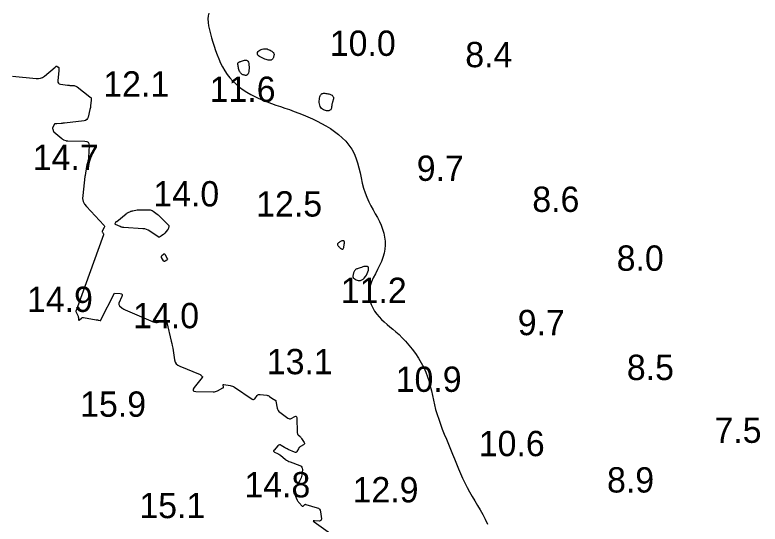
# Model space of a CAD drawing. Extents: x 3040093 to 3056816, y 408076 to 509144.
# Drawn here: x 3044690.5 to 3044837.6, y 435320 to 435420.6 of the extents above; entities that cross this region are included whole.
import ezdxf

# ---------------------------------------------------------------- set-up
doc = ezdxf.new("R2010")
doc.units = 0
for name, color, linetype in [('V-CHAN-CONT-EL12-1112', 7, 'Continuous'), ('V-CHAN-CONT-EL15', 7, 'Continuous'), ('V-TOPO-SOUN-0810', 7, 'Continuous')]:
    doc.layers.add(name, color=color, linetype=linetype)

msp = doc.modelspace()

# ---------------------------------------------------------------- linework, layer by layer
at = {"layer": 'V-CHAN-CONT-EL12-1112'}
msp.add_lwpolyline([(3044728.77, 435420.93), (3044728.62, 435420.39), (3044728.58, 435419.79), (3044728.61, 435419.12), (3044728.71, 435418.41), (3044728.87, 435417.65), (3044729.07, 435416.86), (3044729.3, 435416.05), (3044729.55, 435415.22), (3044729.82, 435414.39), (3044730.1, 435413.55), (3044730.39, 435412.72), (3044730.72, 435411.9), (3044731.07, 435411.09), (3044731.46, 435410.31), (3044731.9, 435409.56), (3044732.38, 435408.84), (3044732.92, 435408.15), (3044733.51, 435407.51), (3044734.15, 435406.91), (3044734.82, 435406.34), (3044735.54, 435405.82), (3044736.28, 435405.33), (3044737.05, 435404.88), (3044737.84, 435404.46), (3044738.64, 435404.08), (3044739.47, 435403.73), (3044740.3, 435403.4), (3044741.15, 435403.09), (3044742.02, 435402.79), (3044742.89, 435402.49), (3044743.78, 435402.19), (3044744.68, 435401.88), (3044745.58, 435401.55), (3044746.5, 435401.21), (3044747.41, 435400.84), (3044748.32, 435400.46), (3044749.23, 435400.05), (3044750.13, 435399.61), (3044751.02, 435399.15), (3044751.89, 435398.66), (3044752.75, 435398.13), (3044753.57, 435397.57), (3044754.36, 435396.97), (3044755.1, 435396.32), (3044755.79, 435395.63), (3044756.41, 435394.89), (3044756.96, 435394.1), (3044757.43, 435393.25), (3044757.81, 435392.34), (3044758.13, 435391.39), (3044758.39, 435390.4), (3044758.62, 435389.4), (3044758.84, 435388.39), (3044759.06, 435387.39), (3044759.3, 435386.41), (3044759.59, 435385.47), (3044759.93, 435384.57), (3044760.32, 435383.71), (3044760.74, 435382.89), (3044761.18, 435382.1), (3044761.62, 435381.32), (3044762.04, 435380.56), (3044762.43, 435379.8), (3044762.78, 435379.05), (3044763.07, 435378.28), (3044763.3, 435377.5), (3044763.46, 435376.72), (3044763.55, 435375.93), (3044763.57, 435375.13), (3044763.51, 435374.33), (3044763.37, 435373.53), (3044763.14, 435372.72), (3044762.83, 435371.91), (3044762.45, 435371.1), (3044762.04, 435370.29), (3044761.63, 435369.49), (3044761.23, 435368.69), (3044760.88, 435367.9), (3044760.6, 435367.12), (3044760.42, 435366.35), (3044760.35, 435365.59), (3044760.4, 435364.84), (3044760.55, 435364.12), (3044760.79, 435363.42), (3044761.11, 435362.75), (3044761.48, 435362.11), (3044761.91, 435361.51), (3044762.38, 435360.96), (3044762.87, 435360.44), (3044763.39, 435359.96), (3044763.94, 435359.49), (3044764.5, 435359.02), (3044765.08, 435358.54), (3044765.69, 435358.03), (3044766.31, 435357.47), (3044766.95, 435356.85), (3044767.6, 435356.15), (3044768.25, 435355.39), (3044768.9, 435354.58), (3044769.53, 435353.72), (3044770.12, 435352.83), (3044770.67, 435351.91), (3044771.17, 435350.98), (3044771.6, 435350.05), (3044771.95, 435349.12), (3044772.24, 435348.21), (3044772.48, 435347.29), (3044772.7, 435346.38), (3044772.89, 435345.46), (3044773.08, 435344.54), (3044773.29, 435343.61), (3044773.53, 435342.67), (3044773.81, 435341.71), (3044774.13, 435340.75), (3044774.48, 435339.77), (3044774.85, 435338.79), (3044775.24, 435337.81), (3044775.65, 435336.82), (3044776.05, 435335.84), (3044776.45, 435334.85), (3044776.85, 435333.88), (3044777.24, 435332.91), (3044777.63, 435331.94), (3044778.02, 435330.99), (3044778.43, 435330.04), (3044778.85, 435329.11), (3044779.29, 435328.19), (3044779.75, 435327.29), (3044780.24, 435326.39), (3044780.75, 435325.51), (3044781.27, 435324.62), (3044781.8, 435323.74), (3044782.32, 435322.84), (3044782.83, 435321.93), (3044783.31, 435321), (3044783.76, 435320.04)], dxfattribs=at)
for points in [[(3044739.8, 435413.92), (3044740.03, 435413.9), (3044740.26, 435413.86), (3044740.48, 435413.79), (3044740.69, 435413.7), (3044740.88, 435413.61), (3044741.05, 435413.51), (3044741.19, 435413.41), (3044741.32, 435413.32), (3044741.42, 435413.24), (3044741.5, 435413.16), (3044741.55, 435413.08), (3044741.6, 435413), (3044741.62, 435412.91), (3044741.63, 435412.82), (3044741.63, 435412.71), (3044741.62, 435412.59), (3044741.59, 435412.47), (3044741.56, 435412.33), (3044741.51, 435412.2), (3044741.46, 435412.07), (3044741.4, 435411.95), (3044741.32, 435411.85), (3044741.24, 435411.76), (3044741.15, 435411.7), (3044741.05, 435411.65), (3044740.93, 435411.63), (3044740.8, 435411.63), (3044740.65, 435411.64), (3044740.47, 435411.68), (3044740.28, 435411.73), (3044740.05, 435411.8), (3044739.81, 435411.88), (3044739.54, 435411.98), (3044739.27, 435412.1), (3044739.02, 435412.22), (3044738.78, 435412.36), (3044738.59, 435412.51), (3044738.44, 435412.66), (3044738.36, 435412.83), (3044738.34, 435413), (3044738.4, 435413.18), (3044738.51, 435413.35), (3044738.66, 435413.5), (3044738.85, 435413.65), (3044739.07, 435413.76), (3044739.31, 435413.85), (3044739.55, 435413.91)], [(3044734.76, 435409.59), (3044734.69, 435409.79), (3044734.64, 435410), (3044734.59, 435410.21), (3044734.55, 435410.42), (3044734.53, 435410.61), (3044734.51, 435410.79), (3044734.51, 435410.94), (3044734.52, 435411.05), (3044734.55, 435411.14), (3044734.59, 435411.21), (3044734.65, 435411.25), (3044734.73, 435411.29), (3044734.82, 435411.33), (3044734.94, 435411.37), (3044735.08, 435411.42), (3044735.24, 435411.48), (3044735.42, 435411.55), (3044735.61, 435411.62), (3044735.8, 435411.66), (3044735.99, 435411.68), (3044736.17, 435411.66), (3044736.33, 435411.58), (3044736.46, 435411.45), (3044736.57, 435411.24), (3044736.64, 435410.98), (3044736.69, 435410.68), (3044736.71, 435410.36), (3044736.71, 435410.03), (3044736.68, 435409.71), (3044736.64, 435409.41), (3044736.58, 435409.16), (3044736.51, 435408.96), (3044736.42, 435408.82), (3044736.33, 435408.72), (3044736.22, 435408.66), (3044736.11, 435408.64), (3044735.99, 435408.64), (3044735.86, 435408.66), (3044735.74, 435408.7), (3044735.61, 435408.74), (3044735.49, 435408.79), (3044735.37, 435408.85), (3044735.25, 435408.92), (3044735.14, 435409.02), (3044735.03, 435409.12), (3044734.93, 435409.26), (3044734.84, 435409.41)], [(3044750.83, 435404.77), (3044750.92, 435404.9), (3044751.02, 435405), (3044751.13, 435405.06), (3044751.25, 435405.1), (3044751.38, 435405.12), (3044751.53, 435405.12), (3044751.69, 435405.11), (3044751.87, 435405.09), (3044752.05, 435405.06), (3044752.25, 435405.03), (3044752.44, 435404.99), (3044752.62, 435404.94), (3044752.79, 435404.88), (3044752.94, 435404.81), (3044753.08, 435404.73), (3044753.18, 435404.64), (3044753.26, 435404.55), (3044753.31, 435404.44), (3044753.35, 435404.33), (3044753.36, 435404.22), (3044753.36, 435404.1), (3044753.35, 435403.98), (3044753.33, 435403.87), (3044753.3, 435403.75), (3044753.27, 435403.64), (3044753.23, 435403.52), (3044753.19, 435403.41), (3044753.15, 435403.3), (3044753.11, 435403.19), (3044753.08, 435403.07), (3044753.06, 435402.96), (3044753.04, 435402.84), (3044753.02, 435402.72), (3044753.02, 435402.6), (3044753.01, 435402.49), (3044753, 435402.38), (3044752.98, 435402.27), (3044752.96, 435402.16), (3044752.93, 435402.06), (3044752.88, 435401.97), (3044752.83, 435401.88), (3044752.75, 435401.81), (3044752.67, 435401.75), (3044752.56, 435401.7), (3044752.44, 435401.66), (3044752.3, 435401.64), (3044752.14, 435401.65), (3044751.97, 435401.67), (3044751.77, 435401.71), (3044751.58, 435401.78), (3044751.38, 435401.87), (3044751.19, 435401.99), (3044751.01, 435402.13), (3044750.86, 435402.31), (3044750.74, 435402.52), (3044750.65, 435402.77), (3044750.59, 435403.03), (3044750.57, 435403.32), (3044750.57, 435403.6), (3044750.59, 435403.89), (3044750.63, 435404.15), (3044750.69, 435404.4), (3044750.75, 435404.61)], [(3044755.2, 435374.33), (3044755.26, 435374.37), (3044755.31, 435374.43), (3044755.36, 435374.53), (3044755.39, 435374.64), (3044755.42, 435374.76), (3044755.44, 435374.9), (3044755.47, 435375.04), (3044755.49, 435375.2), (3044755.51, 435375.35), (3044755.53, 435375.49), (3044755.53, 435375.62), (3044755.52, 435375.75), (3044755.5, 435375.85), (3044755.45, 435375.93), (3044755.38, 435375.98), (3044755.28, 435375.99), (3044755.15, 435375.98), (3044755.02, 435375.95), (3044754.88, 435375.9), (3044754.73, 435375.83), (3044754.59, 435375.76), (3044754.46, 435375.68), (3044754.35, 435375.6), (3044754.27, 435375.53), (3044754.21, 435375.46), (3044754.17, 435375.39), (3044754.16, 435375.32), (3044754.16, 435375.25), (3044754.19, 435375.17), (3044754.24, 435375.09), (3044754.31, 435374.99), (3044754.39, 435374.89), (3044754.49, 435374.78), (3044754.59, 435374.67), (3044754.71, 435374.56), (3044754.82, 435374.47), (3044754.93, 435374.39), (3044755.03, 435374.34), (3044755.12, 435374.32)], [(3044760.19, 435370.82), (3044760.05, 435370.91), (3044759.86, 435370.94), (3044759.63, 435370.93), (3044759.39, 435370.89), (3044759.13, 435370.82), (3044758.88, 435370.74), (3044758.65, 435370.67), (3044758.44, 435370.6), (3044758.25, 435370.54), (3044758.09, 435370.48), (3044757.96, 435370.42), (3044757.83, 435370.36), (3044757.73, 435370.29), (3044757.64, 435370.22), (3044757.56, 435370.13), (3044757.49, 435370.03), (3044757.43, 435369.92), (3044757.38, 435369.8), (3044757.34, 435369.67), (3044757.3, 435369.55), (3044757.27, 435369.42), (3044757.24, 435369.3), (3044757.23, 435369.18), (3044757.21, 435369.08), (3044757.21, 435368.98), (3044757.21, 435368.89), (3044757.23, 435368.81), (3044757.28, 435368.72), (3044757.34, 435368.64), (3044757.42, 435368.55), (3044757.54, 435368.47), (3044757.68, 435368.38), (3044757.85, 435368.29), (3044758.05, 435368.22), (3044758.26, 435368.17), (3044758.49, 435368.15), (3044758.72, 435368.18), (3044758.96, 435368.27), (3044759.2, 435368.42), (3044759.44, 435368.63), (3044759.66, 435368.91), (3044759.87, 435369.22), (3044760.04, 435369.54), (3044760.18, 435369.87), (3044760.27, 435370.18), (3044760.31, 435370.45), (3044760.28, 435370.67)]]:
    msp.add_lwpolyline(points, close=True, dxfattribs=at)
at = {"layer": 'V-CHAN-CONT-EL15'}
for points in [[(3044690.03, 435408.49), (3044694.68, 435408.02), (3044695.13, 435408.01), (3044695.55, 435408.09), (3044695.95, 435408.26), (3044696.32, 435408.52), (3044698.41, 435410.25), (3044698.44, 435410.27), (3044698.47, 435410.3), (3044698.5, 435410.33), (3044698.52, 435410.35), (3044698.63, 435410.46), (3044698.65, 435410.48), (3044698.68, 435410.49), (3044698.71, 435410.49), (3044698.75, 435410.48), (3044699.06, 435410.3), (3044699.11, 435410.26), (3044699.14, 435410.22), (3044699.16, 435410.17), (3044699.17, 435410.11), (3044699.18, 435409.85), (3044699.18, 435409.79), (3044699.18, 435409.72), (3044699.17, 435409.66), (3044699.17, 435409.59), (3044698.98, 435407.55), (3044698.99, 435407.3), (3044699.08, 435407.11), (3044699.24, 435406.98), (3044699.49, 435406.91), (3044700.86, 435406.73), (3044701.03, 435406.71), (3044701.19, 435406.69), (3044701.36, 435406.68), (3044701.52, 435406.66), (3044702.18, 435406.62), (3044702.34, 435406.59), (3044702.49, 435406.55), (3044702.64, 435406.48), (3044702.77, 435406.39), (3044705.26, 435404.42), (3044705.28, 435404.4), (3044705.31, 435404.38), (3044705.34, 435404.36), (3044705.36, 435404.34), (3044705.47, 435404.27), (3044705.5, 435404.25), (3044705.52, 435404.23), (3044705.53, 435404.2), (3044705.53, 435404.17), (3044705.55, 435403.92), (3044705.55, 435403.87), (3044705.55, 435403.82), (3044705.55, 435403.76), (3044705.54, 435403.71), (3044705.43, 435402.68), (3044705.41, 435402.49), (3044705.38, 435402.3), (3044705.34, 435402.12), (3044705.3, 435401.93), (3044704.95, 435400.41), (3044704.85, 435400.13), (3044704.68, 435399.91), (3044704.45, 435399.77), (3044704.16, 435399.7), (3044700.25, 435399.23), (3044700.1, 435399.21), (3044699.94, 435399.19), (3044699.79, 435399.18), (3044699.63, 435399.16), (3044698.79, 435399.05), (3044698.74, 435399.05), (3044698.7, 435399.05), (3044698.65, 435399.05), (3044698.61, 435399.06), (3044698.43, 435399.1), (3044698.39, 435399.1), (3044698.35, 435399.09), (3044698.32, 435399.07), (3044698.3, 435399.03), (3044697.93, 435398.31), (3044697.92, 435398.27), (3044697.91, 435398.24), (3044697.91, 435398.2), (3044697.92, 435398.17), (3044697.98, 435398.02), (3044698, 435397.98), (3044698.01, 435397.95), (3044698.02, 435397.91), (3044698.03, 435397.87), (3044698.07, 435397.66), (3044698.08, 435397.62), (3044698.1, 435397.58), (3044698.13, 435397.54), (3044698.16, 435397.51), (3044699.73, 435396.17), (3044699.82, 435396.1), (3044699.91, 435396.04), (3044700.01, 435395.99), (3044700.11, 435395.94), (3044700.52, 435395.78), (3044700.63, 435395.75), (3044700.73, 435395.72), (3044700.84, 435395.7), (3044700.95, 435395.7), (3044704.31, 435395.67), (3044704.68, 435395.62), (3044704.94, 435395.46), (3044705.09, 435395.19), (3044705.13, 435394.81), (3044705.04, 435392.45), (3044705.03, 435392.35), (3044705.02, 435392.26), (3044705.01, 435392.17), (3044704.99, 435392.08), (3044704.9, 435391.71), (3044704.88, 435391.62), (3044704.86, 435391.53), (3044704.83, 435391.45), (3044704.81, 435391.36), (3044704.71, 435391.01), (3044704.69, 435390.93), (3044704.67, 435390.84), (3044704.65, 435390.75), (3044704.63, 435390.66), (3044704.35, 435388.85), (3044704.35, 435388.84), (3044704.34, 435388.82), (3044704.34, 435388.81), (3044704.34, 435388.79), (3044704.32, 435388.74), (3044704.31, 435388.72), (3044704.31, 435388.71), (3044704.31, 435388.69), (3044704.31, 435388.68), (3044703.87, 435384.94), (3044703.86, 435384.33), (3044703.98, 435383.77), (3044704.22, 435383.25), (3044704.59, 435382.76), (3044708.06, 435379.09), (3044708.14, 435378.98), (3044708.18, 435378.86), (3044708.17, 435378.73), (3044708.12, 435378.6), (3044707.74, 435377.92), (3044707.71, 435377.86), (3044707.7, 435377.79), (3044707.72, 435377.73), (3044707.75, 435377.67), (3044707.93, 435377.43), (3044707.97, 435377.36), (3044707.99, 435377.3), (3044707.99, 435377.23), (3044707.97, 435377.16), (3044702.55, 435362.25)], [(3044702.55, 435362.25), (3044702.54, 435362.23), (3044702.51, 435362.18), (3044702.49, 435362.13), (3044702.49, 435362.08), (3044702.51, 435362.03), (3044702.95, 435361.1), (3044702.99, 435361.02), (3044703.01, 435360.94), (3044703.03, 435360.85), (3044703.04, 435360.76), (3044703.07, 435360.41), (3044703.08, 435360.34), (3044703.11, 435360.3), (3044703.15, 435360.31), (3044703.21, 435360.35), (3044703.61, 435360.73), (3044703.7, 435360.8), (3044703.8, 435360.84), (3044703.91, 435360.86), (3044704.02, 435360.85), (3044706.56, 435360.4), (3044706.66, 435360.39), (3044706.75, 435360.37), (3044706.84, 435360.35), (3044706.94, 435360.33), (3044707.32, 435360.25), (3044707.39, 435360.25), (3044707.44, 435360.27), (3044707.45, 435360.32), (3044707.44, 435360.39), (3044710.17, 435365.63)], [(3044710.17, 435365.63), (3044711.27, 435365.55), (3044711.51, 435365.5), (3044711.65, 435365.38), (3044711.68, 435365.21), (3044711.61, 435364.97), (3044711.02, 435363.68), (3044710.98, 435363.53), (3044710.98, 435363.39), (3044711.04, 435363.26), (3044711.15, 435363.15), (3044711.68, 435362.7), (3044711.81, 435362.6), (3044711.96, 435362.5), (3044712.11, 435362.42), (3044712.26, 435362.35), (3044717.78, 435359.98), (3044718.03, 435359.89), (3044718.28, 435359.86), (3044718.54, 435359.87), (3044718.8, 435359.92), (3044719.84, 435360.24), (3044720.07, 435360.28), (3044720.26, 435360.23), (3044720.39, 435360.1), (3044720.48, 435359.88), (3044721.36, 435356.2), (3044721.46, 435355.74), (3044721.56, 435355.28), (3044721.64, 435354.81), (3044721.72, 435354.35), (3044722, 435352.48), (3044722.12, 435352.05), (3044722.33, 435351.7), (3044722.63, 435351.41), (3044723.02, 435351.2), (3044727.04, 435349.57), (3044727.1, 435349.54), (3044727.16, 435349.5), (3044727.21, 435349.46), (3044727.27, 435349.41), (3044727.47, 435349.22), (3044727.5, 435349.17), (3044727.52, 435349.12), (3044727.51, 435349.07), (3044727.48, 435349.01), (3044725.86, 435346.99), (3044725.66, 435346.68), (3044725.66, 435346.45), (3044725.83, 435346.31), (3044726.2, 435346.26), (3044729.65, 435346.17), (3044729.88, 435346.18), (3044730.09, 435346.22), (3044730.3, 435346.28), (3044730.51, 435346.37), (3044731.56, 435346.94), (3044731.62, 435346.98), (3044731.66, 435347.03), (3044731.67, 435347.1), (3044731.66, 435347.17), (3044731.58, 435347.49), (3044731.57, 435347.56), (3044731.59, 435347.6), (3044731.63, 435347.62), (3044731.7, 435347.62), (3044732.96, 435347.42), (3044733.2, 435347.37), (3044733.42, 435347.29), (3044733.63, 435347.2), (3044733.83, 435347.07), (3044737.3, 435344.73), (3044737.45, 435344.65), (3044737.59, 435344.64), (3044737.72, 435344.7), (3044737.84, 435344.81), (3044738.29, 435345.41), (3044738.41, 435345.54), (3044738.55, 435345.62), (3044738.71, 435345.67), (3044738.89, 435345.66), (3044740.2, 435345.5), (3044740.35, 435345.47), (3044740.5, 435345.42), (3044740.63, 435345.36), (3044740.76, 435345.27), (3044741.42, 435344.78), (3044741.47, 435344.74), (3044741.52, 435344.71), (3044741.58, 435344.68), (3044741.64, 435344.65), (3044741.87, 435344.54), (3044741.93, 435344.5), (3044741.97, 435344.46), (3044742, 435344.41), (3044742.01, 435344.35), (3044742.27, 435342.96), (3044742.34, 435342.72), (3044742.44, 435342.5), (3044742.59, 435342.31), (3044742.78, 435342.14), (3044744.37, 435340.96), (3044744.53, 435340.87), (3044744.7, 435340.83), (3044744.87, 435340.84), (3044745.04, 435340.91), (3044745.75, 435341.3), (3044745.91, 435341.36), (3044746.02, 435341.34), (3044746.09, 435341.25), (3044746.12, 435341.09), (3044746.22, 435338.05), (3044746.24, 435337.94), (3044746.27, 435337.83), (3044746.33, 435337.74), (3044746.41, 435337.65), (3044746.78, 435337.34), (3044746.86, 435337.25), (3044746.94, 435337.17), (3044747.02, 435337.07), (3044747.08, 435336.97), (3044747.57, 435336.16), (3044747.63, 435336.02), (3044747.62, 435335.91), (3044747.57, 435335.8), (3044747.46, 435335.72), (3044746.89, 435335.39), (3044746.76, 435335.3), (3044746.65, 435335.2), (3044746.55, 435335.08), (3044746.46, 435334.94), (3044746.15, 435334.38), (3044746.06, 435334.26), (3044745.96, 435334.2), (3044745.84, 435334.19), (3044745.7, 435334.23), (3044744.44, 435334.79), (3044744.25, 435334.88), (3044744.07, 435334.97), (3044743.89, 435335.07), (3044743.72, 435335.17), (3044743.03, 435335.6), (3044742.86, 435335.67), (3044742.7, 435335.68), (3044742.55, 435335.63), (3044742.41, 435335.51), (3044741.63, 435334.67), (3044741.55, 435334.55), (3044741.53, 435334.45), (3044741.58, 435334.36), (3044741.7, 435334.28), (3044742.32, 435333.99), (3044742.47, 435333.91), (3044742.61, 435333.83), (3044742.75, 435333.73), (3044742.89, 435333.63), (3044743.89, 435332.83), (3044744.1, 435332.67), (3044744.33, 435332.53), (3044744.57, 435332.41), (3044744.81, 435332.31), (3044746.76, 435331.6), (3044746.99, 435331.48), (3044747.14, 435331.31), (3044747.22, 435331.1), (3044747.23, 435330.84), (3044747.11, 435329.72), (3044747.06, 435329.44), (3044746.99, 435329.17), (3044746.88, 435328.92), (3044746.75, 435328.67), (3044745.87, 435327.27), (3044745.84, 435327.2), (3044745.8, 435327.14), (3044745.77, 435327.07), (3044745.74, 435327), (3044745.61, 435326.62), (3044745.6, 435326.61), (3044745.59, 435326.59), (3044745.57, 435326.58), (3044745.56, 435326.57), (3044745.48, 435326.54), (3044745.46, 435326.53), (3044745.45, 435326.51), (3044745.45, 435326.5), (3044745.46, 435326.48), (3044746.2, 435324.79), (3044746.28, 435324.64), (3044746.37, 435324.49), (3044746.47, 435324.36), (3044746.58, 435324.23), (3044747.21, 435323.62), (3044747.26, 435323.58), (3044747.32, 435323.57), (3044747.37, 435323.59), (3044747.43, 435323.63), (3044747.64, 435323.87), (3044747.7, 435323.92), (3044747.76, 435323.95), (3044747.83, 435323.96), (3044747.9, 435323.95), (3044750.13, 435323.29), (3044750.4, 435323.18), (3044750.6, 435323), (3044750.74, 435322.78), (3044750.81, 435322.49), (3044750.98, 435321.08), (3044750.97, 435320.88), (3044750.9, 435320.74), (3044750.77, 435320.66), (3044750.56, 435320.64), (3044749.63, 435320.71), (3044749.44, 435320.71), (3044749.37, 435320.67), (3044749.4, 435320.59), (3044749.54, 435320.47), (3044753.24, 435317.84)]]:
    msp.add_lwpolyline(points, dxfattribs=at)
for points in [[(3044720.75, 435378.36), (3044720.72, 435378.28), (3044720.67, 435378.21), (3044720.62, 435378.13), (3044720.08, 435377.51), (3044720.02, 435377.44), (3044719.95, 435377.38), (3044719.89, 435377.32), (3044719.82, 435377.26), (3044719.5, 435377.02), (3044719.44, 435376.98), (3044719.38, 435376.94), (3044719.32, 435376.9), (3044719.26, 435376.86), (3044719.01, 435376.73), (3044718.95, 435376.7), (3044718.89, 435376.7), (3044718.83, 435376.71), (3044718.77, 435376.74), (3044717.1, 435377.91), (3044716.79, 435378.1), (3044716.47, 435378.24), (3044716.13, 435378.33), (3044715.77, 435378.37), (3044712, 435378.6), (3044711.81, 435378.62), (3044711.63, 435378.65), (3044711.45, 435378.71), (3044711.28, 435378.78), (3044710.36, 435379.23), (3044710.32, 435379.26), (3044710.29, 435379.3), (3044710.28, 435379.34), (3044710.29, 435379.4), (3044710.38, 435379.69), (3044710.39, 435379.71), (3044710.4, 435379.72), (3044710.42, 435379.74), (3044710.44, 435379.75), (3044710.52, 435379.78), (3044710.54, 435379.79), (3044710.56, 435379.8), (3044710.58, 435379.82), (3044710.6, 435379.83), (3044712.43, 435381.33), (3044712.53, 435381.41), (3044712.63, 435381.47), (3044712.73, 435381.53), (3044712.84, 435381.59), (3044713.28, 435381.79), (3044713.39, 435381.84), (3044713.5, 435381.87), (3044713.62, 435381.91), (3044713.74, 435381.93), (3044714.59, 435382.07), (3044714.77, 435382.1), (3044714.96, 435382.12), (3044715.14, 435382.13), (3044715.32, 435382.13), (3044716.96, 435382.13), (3044717.19, 435382.11), (3044717.41, 435382.06), (3044717.61, 435381.97), (3044717.81, 435381.84), (3044718.55, 435381.26), (3044718.74, 435381.12), (3044718.92, 435380.96), (3044719.09, 435380.8), (3044719.26, 435380.64), (3044720.77, 435379.12), (3044720.82, 435379.05), (3044720.85, 435378.98), (3044720.87, 435378.9), (3044720.86, 435378.81), (3044720.78, 435378.45)], [(3044720.61, 435372.41), (3044720.61, 435372.33), (3044720.57, 435372.26), (3044720.5, 435372.19), (3044720.12, 435371.96), (3044720.03, 435371.92), (3044719.95, 435371.92), (3044719.88, 435371.96), (3044719.82, 435372.03), (3044719.44, 435372.71), (3044719.4, 435372.8), (3044719.4, 435372.89), (3044719.43, 435372.98), (3044719.49, 435373.06), (3044719.8, 435373.36), (3044719.87, 435373.42), (3044719.94, 435373.43), (3044720.01, 435373.4), (3044720.06, 435373.33), (3044720.57, 435372.5)]]:
    msp.add_lwpolyline(points, close=True, dxfattribs=at)

# ---------------------------------------------------------------- texts
at = {"layer": 'V-TOPO-SOUN-0810'}
for s, p in [('10.0 ', (3044752.64, 435412.5)), ('8.4', (3044779.38, 435410.26)), ('12.1 ', (3044707.93, 435404.46)), ('11.6 ', (3044728.92, 435403.41)), ('14.7 ', (3044694.02, 435389.96)), ('9.7', (3044769.8, 435387.82)), ('14.0 ', (3044717.8, 435382.77)), ('8.6', (3044792.61, 435381.69)), ('12.5 ', (3044738.11, 435380.77)), ('8.0', (3044809.26, 435370.07)), ('11.2 ', (3044754.81, 435363.71)), ('14.9 ', (3044692.87, 435361.94)), ('14.0 ', (3044713.83, 435358.72)), ('9.7', (3044789.74, 435357.35)), ('13.1 ', (3044740.21, 435349.64)), ('8.5', (3044811.27, 435348.49)), ('10.9 ', (3044765.64, 435346.16)), ('15.9 ', (3044703.37, 435341.24)), ('7.5', (3044828.56, 435336.09)), ('10.6 ', (3044782.04, 435333.46)), ('8.9', (3044807.36, 435326.28)), ('14.8 ', (3044735.78, 435325.32)), ('12.9 ', (3044757.14, 435324.34)), ('15.1 ', (3044715.05, 435321.22))]:
    msp.add_text(s, height=5, dxfattribs=at).set_placement(p)

doc.saveas('drawing.dxf')
